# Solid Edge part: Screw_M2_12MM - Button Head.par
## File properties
Author: hhakima
Template: Normal.par
Last saved by: hhakima
Revision: 7
Application: Solid Edge
Density: 7833.000 kg/m^3
Accuracy: 0.990
Material: Steel
Face Style: Steel
Fill Style: ANSI32(Steel)
Virtual Style: Machined steel
Coef. of Thermal Exp: 1.3e-05
Thermal Conductivity: 32.0
Specific Heat: 481.0
Modulus of Elasticity: 199947953000.0
Poission's Ratio: 0.29
Yield Stress: 262000766.0
Ultimate Stress: 358527364.0
Elongation: 0.0
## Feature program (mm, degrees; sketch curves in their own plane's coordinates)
body "unnamed Body 1"
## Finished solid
Body 1: solid body, 22 faces, 51 edges, 32 vertices.
  Faces by surface: plane 9, cone 7, cylinder 3, spline 2, torus 1
  Edges by curve: intersection 22, circle 13, line 12, spline 4
Bounding box of the edges (mm; curved faces can reach further): 3.500 x 3.500 x 13.296, from (-1.75, -1.75, -13.296) to (1.75, 1.75, 0).
Cylindrical faces by radius (mm): R0.7402 x1, R1 x1, R1.75 x1
Conical faces (half-angle, radius in mm at the cone's reference point): 45 deg R0.7506 x6, 55 deg R0.4862 x1
Toroidal faces (ring radius, tube radius in mm): R0.65 r1.1563 x1
Planar faces by outward normal: +x 1, +z 2, -x 1, -z 1, oblique 4
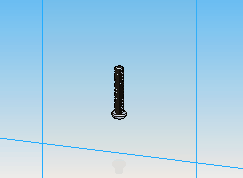
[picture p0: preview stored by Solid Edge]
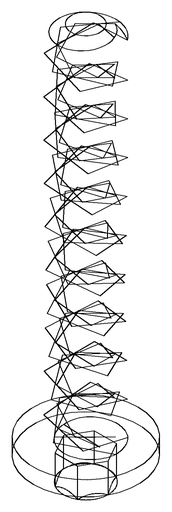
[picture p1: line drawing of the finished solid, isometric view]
